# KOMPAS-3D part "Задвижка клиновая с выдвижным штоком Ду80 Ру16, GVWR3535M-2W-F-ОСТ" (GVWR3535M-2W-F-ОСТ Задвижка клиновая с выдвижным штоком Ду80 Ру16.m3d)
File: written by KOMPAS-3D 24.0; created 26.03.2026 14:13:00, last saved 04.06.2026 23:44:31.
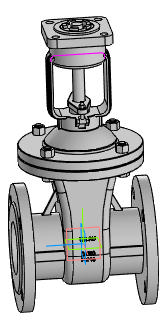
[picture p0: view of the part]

Document properties: Автор: R2D2; Полное имя файла: E:\Работа\Зайцев\GVWR3535M-2W-F-ОСТ Задвижка клиновая 30нж941нж DN.ru Ду50-200 Ру16\исходные данные\DN80\Исходные материалы\GVWR3535M-2W-F-ОСТ Задвижка клиновая с выдвижным штоком Ду80 Ру16.m3d

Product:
- Component [detail]: AS 1110 - M12 x 45  | qty 4  | pos. 2  | Комментарий: Болты и винты   шестигранные точные   метрические ISO; Автор: R2D2; additional columns: Сталь, мягкая; source file: AS 1110 - M12 x 45 AS 1110 - M12 x 45.m3d
- Component [detail]: ANSI B18.2.4.2M - M12x1,75 - 18  | designation ANSI B18.2.4.2M - M12x1,75  | qty 4  | pos. 3  | Комментарий: Типы метрических   шестигранных гаек   2; Автор: R2D2; additional columns: Сталь, мягкая; source file: ANSI B18.2.4.2M - M12x1,75 ANSI B18.2.4.2M - M12x1,75 - 18.m3d
- Component [detail]: ANSI B18.2.4.2M - M5x0,8 - 8  | designation ANSI B18.2.4.2M - M5x0,8  | qty 2  | pos. 4  | Комментарий: Типы метрических   шестигранных гаек   2; Автор: R2D2; additional columns: Сталь, мягкая; source file: ANSI B18.2.4.2M - M5x0,8 ANSI B18.2.4.2M - M5x0,8 - 8.m3d
- Component [detail]: Деталь1  | qty 1  | pos. 5  | additional columns: Типовые; source file: 2.m3d
- Component [detail]: Фланец  | qty 2  | pos. 5  | Автор: R2D2; additional columns: Типовые; source file: Фланец DN80 PN16 b20.m3d
- Component [assembly]: DN50_3D_STEP  | designation Сборка  | qty 1  | pos. 6  | Масса: 2.725126; Автор: R2D2; source file: Фланец А.a3d
- Body: Тело 2  | qty 1
    Масса: 33.644034
- Body: Тело 3  | qty 1
    Масса: 33.644034
- Part/product: Задвижка клиновая с выдвижным штоком Ду80 Ру16  | designation GVWR3535M-2W-F-ОСТ
    Масса: 20.5
    Раздел спецификации: Прочие изделия
    Примечание: D040-09830

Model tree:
1. Массив по концентрической сетке:1  (labels: Грань.Твердое тело1)  (4 pattern instances)
     Шаг 2 = 360
2. Массив по концентрической сетке:2  (labels: Грань.Твердое тело1)  (2 pattern instances)
     Шаг 2 = 360
3. Элемент выдавливания:3  (with: Грань.Элемент выдавливания:2, Грань.Элемент вращения:1)
     Расстояние 1 = 9.70585
4. Элемент выдавливания:4  (with: Грань.Элемент выдавливания:3, Грань.Элемент вращения:1)
     Расстояние 1 = 4.75074
5. Элемент выдавливания:5  (with: Грань.Элемент выдавливания:3)
     Расстояние 1 = 10
6. Эскиз:2  (with: Вершина.Элемент выдавливания:5, Ребро.Элемент выдавливания:3)
7. Элемент по траектории:1  (with: Грань.Элемент выдавливания:5)
     Толщина стенки 1 = 1; Длина траектории = 97.708
8. Элемент выдавливания:6  (with: Грань.Элемент выдавливания:3, Грань.Элемент по траектории:1)
     Расстояние 1 = 68.421
9. Эскиз:3  (with: Ребро.Элемент выдавливания:4, Ребро.Элемент выдавливания:3)
10. Элемент вращения:1
     Угол 1 = 360
11. Фаска:1  (with: Ребро.Элемент вращения:1)
     Угол = 45; Длина 1 = 3; Длина 2 = 3
12. Эскиз:4
13. Элемент выдавливания:7  (with: Грань.Элемент выдавливания:3, Грань.Элемент вращения:1, Грань.Операция без истории:2)  (labels: Грань.Твердое тело1; Грань.Solid1; Solid1; Твердое тело1)
     Расстояние 1 = 61; Смещение 1 = 1; Расстояние = -105; Ориентация = 2; Расстояние = -349

Expressions: 135+6
Referenced files in E:\Работа\Зайцев\GVWR3535M-2W-F-ОСТ Задвижка клиновая 30нж941нж DN.ru Ду50-200 Ру16\исходные данные\DN80\Исходные материалы\: AS 1110 - M12 x 45 AS 1110 - M12 x 45.m3d, ANSI B18.2.4.2M - M12x1,75 ANSI B18.2.4.2M - M12x1,75 - 18.m3d, ANSI B18.2.4.2M - M5x0,8 ANSI B18.2.4.2M - M5x0,8 - 8.m3d, 2.m3d, Фланец DN80 PN16 b20.m3d, Фланец А.a3d
Referenced files in E:\Работа\Зайцев\GVWR2626M-2W-F-S Задвижка клиновая с выдвижным штоком DN.ru Ду50-300 Ру16\DN80\исходные материалы\: Фланец DN80 PN16 b20.m3d
Referenced files in E:\Работа\Зайцев\GVWR3131M-2W-F-S Задвижка клиновая с выдвижным штоком DN.ru Ду50-200 Ру63\DN80\исходные материалы\: ANSI B18.2.4.2M - M12x1,75 ANSI B18.2.4.2M - M12x1,75 - 18.m3d, AS 1110 - M12 x 45 AS 1110 - M12 x 45.m3d, ANSI B18.2.4.2M - M5x0,8 ANSI B18.2.4.2M - M5x0,8 - 8.m3d
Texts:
  GVWR3535M-2W-F-ОСТ
  DN80
  GOST 26.020 Pr3
  PN16
  AS 1110 - M12 x 45 AS 1110 - M12 x 45 (1)
  ANSI B18.2.4.2M - M12x1,75 ANSI B18.2.4.2M - M12x1,75 - 18 (1)
  ANSI B18.2.4.2M - M5x0,8 ANSI B18.2.4.2M - M5x0,8 - 8 (1)
  Деталь1 Деталь1
  Фланец (1)
  Фланец (2)
  ANSI B18.2.4.2M - M12x1,75 ANSI B18.2.4.2M - M12x1,75 - 18 (2)
  AS 1110 - M12 x 45 AS 1110 - M12 x 45 (2)
  ANSI B18.2.4.2M - M12x1,75 ANSI B18.2.4.2M - M12x1,75 - 18 (3)
  AS 1110 - M12 x 45 AS 1110 - M12 x 45 (3)
  ANSI B18.2.4.2M - M12x1,75 ANSI B18.2.4.2M - M12x1,75 - 18 (4)
  AS 1110 - M12 x 45 AS 1110 - M12 x 45 (4)
  ANSI B18.2.4.2M - M5x0,8 ANSI B18.2.4.2M - M5x0,8 - 8 (2)
  Сборка DN50_3D_STEP
  Ось Y.Начало координат
  Ось Z.Начало координат
  Плоскость ZX.Начало координат
  Плоскость XY.Начало координат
